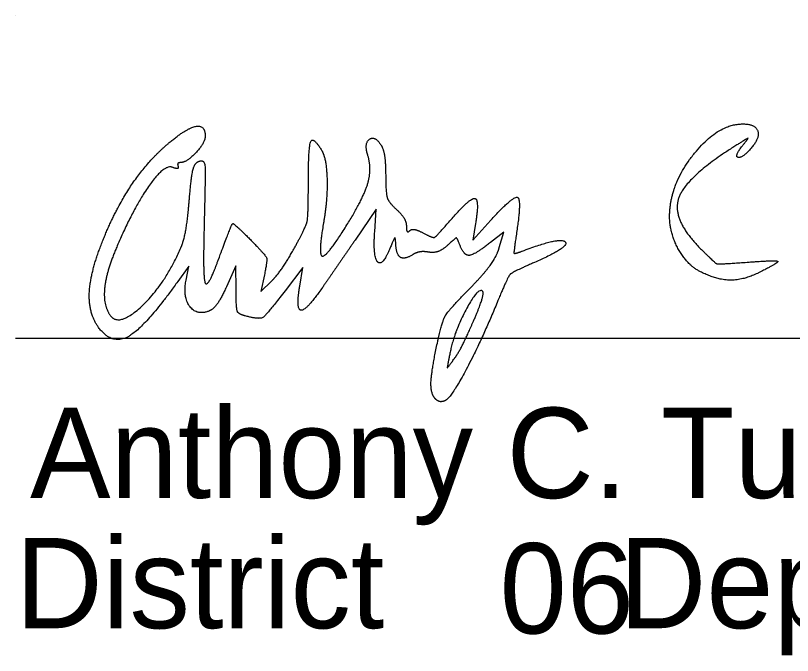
# Model space of a CAD drawing. Extents: x 0 to 34, y 0 to 22.
# Drawn here: x 24.5 to 25.705, y 8.324 to 9.316 of the extents above; entities that cross this region are included whole.
import ezdxf

# ---------------------------------------------------------------- set-up
doc = ezdxf.new("R2010")
doc.units = 0
doc.layers.add('SH_Data', color=7, linetype='Continuous')
doc.layers.add('SH_Text', color=7, linetype='Continuous')

msp = doc.modelspace()

# ---------------------------------------------------------------- linework, layer by layer
at = {"layer": 'SH_Data'}
for p, q in [((24.5, 9.316), (24.5, 9.316)), ((24.5, 8.816), (28, 8.816))]:
    msp.add_line(p, q, dxfattribs=at)
at = {"layer": 'SH_Text'}
for p, q in [((25.5635, 8.918), (25.5635, 8.918)), ((25.2102, 8.8422), (25.2102, 8.8422)), ((25.1516, 8.7211), (25.1516, 8.7211))]:
    msp.add_line(p, q, dxfattribs=at)
for points in [[(25.057, 8.9805), (25.0594, 9.0159), (25.0266, 8.9679)], [(25.2133, 8.9936), (25.209, 8.9679), (25.2371, 8.9987)], [(25.2502, 8.9563), (25.2571, 8.9803), (25.2365, 8.9641)], [(24.7644, 8.9055), (24.7686, 8.9276), (24.7516, 8.9038)], [(24.8419, 8.8909), (24.8418, 8.9279), (24.8269, 8.8952)], [(24.9407, 8.8966), (24.9453, 8.9252), (24.9179, 8.8893)], [(24.886, 8.9142), (24.8806, 8.8879), (24.8967, 8.9039)]]:
    msp.add_lwpolyline(points, dxfattribs=at)
for points in [[(24.7383, 9.1189), (24.7651, 9.1414), (24.7941, 9.1468), (24.7941, 9.1292)], [(25.5143, 9.0056), (25.5148, 9.0547), (25.5892, 9.1479), (25.6278, 9.1479)], [(25.6278, 9.1479), (25.6467, 9.1479), (25.6549, 9.1273), (25.642, 9.1118)], [(24.7941, 9.1292), (24.7941, 9.1186), (24.7653, 9.0879), (24.7553, 9.0879)], [(24.9541, 9.0555), (24.9541, 9.1114), (24.9611, 9.129), (24.9747, 9.107)], [(25.0462, 9.0997), (25.0404, 9.1179), (25.0572, 9.1303), (25.0669, 9.115)], [(25.6271, 9.1138), (25.6367, 9.1259), (25.6351, 9.1258), (25.6141, 9.1125)], [(24.6343, 8.9643), (24.6544, 9.0155), (24.7054, 9.0911), (24.7383, 9.1189)], [(25.0669, 9.115), (25.0707, 9.1089), (25.0739, 9.0874), (25.074, 9.0672)], [(25.6141, 9.1125), (25.5388, 9.065), (25.5174, 8.9994), (25.5624, 8.9544)], [(25.642, 9.1118), (25.6281, 9.0951), (25.6138, 9.0969), (25.6271, 9.1138)], [(24.9747, 9.107), (24.9822, 9.0949), (24.9839, 9.0305), (24.9776, 8.9945)], [(25.0096, 8.9845), (25.0378, 9.0289), (25.0532, 9.0775), (25.0462, 9.0997)], [(24.7553, 9.0879), (24.7524, 9.0879), (24.751, 9.0854), (24.752, 9.0822)], [(24.7696, 9.0313), (24.7725, 9.0666), (24.7779, 9.0879), (24.7846, 9.0901)], [(24.7846, 9.0901), (24.7929, 9.0929), (24.7946, 9.0739), (24.7926, 8.9968)], [(24.7431, 9.0807), (24.7305, 9.0855), (24.6827, 9.0173), (24.6576, 8.9587)], [(24.752, 9.0822), (24.7531, 9.0791), (24.7491, 9.0784), (24.7431, 9.0807)], [(25.074, 9.0672), (25.0741, 9.0407), (25.0786, 9.0264), (25.0901, 9.0159)], [(24.9335, 8.9575), (24.9505, 8.9885), (24.9541, 9.0055), (24.9541, 9.0555)], [(24.7564, 8.9559), (24.7612, 8.9669), (24.7671, 9.0009), (24.7696, 9.0313)], [(25.1753, 8.9996), (25.2047, 9.0336), (25.2196, 9.0313), (25.2133, 8.9936)], [(25.2371, 8.9987), (25.2719, 9.0369), (25.2848, 9.0315), (25.2774, 8.982)], [(25.0901, 9.0159), (25.0989, 9.008), (25.1061, 8.996), (25.1061, 8.9894)], [(25.5635, 8.918), (25.5423, 8.9282), (25.514, 8.9785), (25.5143, 9.0056)], [(24.7926, 8.9968), (24.7912, 8.9435), (24.7925, 8.8999), (24.7955, 8.8999)], [(24.8148, 8.9379), (24.8348, 8.9923), (24.8388, 8.9944), (24.8668, 8.9658)], [(24.9776, 8.9945), (24.969, 8.945), (24.982, 8.9409), (25.0096, 8.9845)], [(25.1061, 8.9894), (25.1061, 8.9827), (25.1084, 8.9796), (25.1112, 8.9823)], [(25.1328, 8.9785), (25.1472, 8.9708), (25.1528, 8.9736), (25.1753, 8.9996)], [(25.0816, 8.9573), (25.0693, 8.9266), (25.0542, 8.9408), (25.057, 8.9805)], [(25.1112, 8.9823), (25.1139, 8.9851), (25.1237, 8.9834), (25.1328, 8.9785)], [(25.2774, 8.982), (25.2725, 8.9494), (25.2734, 8.946), (25.2858, 8.9507)], [(24.6289, 8.8323), (24.6131, 8.8538), (24.6157, 8.9173), (24.6343, 8.9643)], [(24.8668, 8.9658), (24.8879, 8.9442), (24.8907, 8.9366), (24.886, 8.9142)], [(25.0266, 8.9679), (25.0085, 8.9415), (24.9857, 8.9084), (24.9759, 8.8943)], [(25.0896, 8.9624), (25.0893, 8.9719), (25.0869, 8.9704), (25.0816, 8.9573)], [(25.1889, 8.9603), (25.1847, 8.9713), (25.1826, 8.9712), (25.1698, 8.9597)], [(25.2365, 8.9641), (25.212, 8.9448), (25.1953, 8.9435), (25.1889, 8.9603)], [(25.2858, 8.9507), (25.3453, 8.9735), (25.3596, 8.9566), (25.3017, 8.9318)], [(24.6576, 8.9587), (24.6411, 8.9202), (24.6354, 8.8693), (24.6457, 8.8526)], [(24.6457, 8.8526), (24.659, 8.8311), (24.7316, 8.8988), (24.7564, 8.9559)], [(24.8967, 8.9039), (24.9055, 8.9127), (24.9221, 8.9368), (24.9335, 8.9575)], [(25.1161, 8.9453), (25.1031, 8.9371), (25.0903, 8.9454), (25.0896, 8.9624)], [(25.1698, 8.9597), (25.1619, 8.9525), (25.1489, 8.9478), (25.1408, 8.9491)], [(25.2033, 8.8916), (25.2253, 8.914), (25.2464, 8.9431), (25.2502, 8.9563)], [(25.5624, 8.9544), (25.5852, 8.9317), (25.5899, 8.9303), (25.6344, 8.9335)], [(25.1408, 8.9491), (25.1327, 8.9505), (25.1216, 8.9487), (25.1161, 8.9453)], [(24.7955, 8.8999), (24.7984, 8.8999), (24.8071, 8.917), (24.8148, 8.9379)], [(25.3017, 8.9318), (25.2703, 8.9183), (25.263, 8.9104), (25.2481, 8.8741)], [(25.6344, 8.9335), (25.6607, 8.9354), (25.6821, 8.9359), (25.6821, 8.9347)], [(25.6821, 8.9347), (25.6821, 8.9334), (25.6715, 8.9269), (25.6585, 8.9202)], [(25.6585, 8.9202), (25.6312, 8.906), (25.5903, 8.9051), (25.5635, 8.918)], [(24.7516, 8.9038), (24.702, 8.834), (24.6498, 8.8036), (24.6289, 8.8323)], [(24.7998, 8.8577), (24.781, 8.8505), (24.7594, 8.8796), (24.7644, 8.9055)], [(24.8269, 8.8952), (24.8187, 8.8771), (24.8065, 8.8603), (24.7998, 8.8577)], [(24.9759, 8.8943), (24.9511, 8.8585), (24.9347, 8.8596), (24.9407, 8.8966)], [(25.1547, 8.811), (25.1614, 8.8422), (25.172, 8.8598), (25.2033, 8.8916)], [(24.8561, 8.8502), (24.8454, 8.853), (24.8421, 8.8624), (24.8419, 8.8909)], [(24.9179, 8.8893), (24.8887, 8.851), (24.8783, 8.8444), (24.8561, 8.8502)], [(25.2242, 8.8886), (25.2175, 8.8952), (25.1806, 8.8264), (25.1744, 8.7959)], [(25.2102, 8.8422), (25.2201, 8.8654), (25.2264, 8.8863), (25.2242, 8.8886)], [(25.2481, 8.8741), (25.2229, 8.8124), (25.1745, 8.7214), (25.1652, 8.7183)], [(25.1804, 8.7839), (25.1868, 8.7927), (25.2002, 8.819), (25.2102, 8.8422)], [(25.1516, 8.7211), (25.1436, 8.7291), (25.1449, 8.7653), (25.1547, 8.811)], [(25.1744, 8.7959), (25.1691, 8.77), (25.1696, 8.7691), (25.1804, 8.7839)], [(25.1652, 8.7183), (25.1607, 8.7168), (25.1546, 8.7181), (25.1516, 8.7211)]]:
    msp.add_open_spline(points, degree=2, dxfattribs=at)

# ---------------------------------------------------------------- texts
for s, p in [('Anthony C. Turowski, P.E.', (24.5225, 8.5679)), ('District       Deputy Director', (24.5, 8.366)), ('              06', (24.5225, 8.3579))]:
    msp.add_text(s, height=0.14, dxfattribs=at).set_placement(p)

doc.saveas('drawing.dxf')
